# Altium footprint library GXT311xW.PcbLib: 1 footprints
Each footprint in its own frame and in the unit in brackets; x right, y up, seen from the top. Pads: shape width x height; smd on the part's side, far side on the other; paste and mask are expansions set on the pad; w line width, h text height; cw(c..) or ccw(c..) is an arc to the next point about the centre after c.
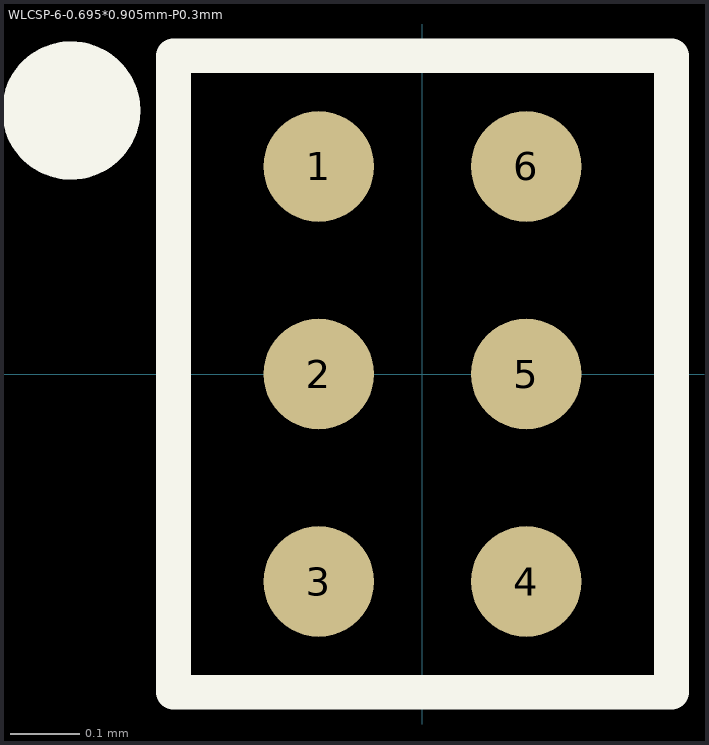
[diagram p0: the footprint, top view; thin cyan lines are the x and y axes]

## WLCSP-6-0.695*0.905mm-P0.3mm [mm]
height 0.55
pads (6):
  round 0.16 smd mask+0.05: 1(-0.15,0.3) 2(-0.15,0) 3(-0.15,-0.3) 4(0.15,-0.3) 5(0.15,0) 6(0.15,0.3)
Top Overlay:
  circle w0.1: c-0.508,0.381 r0.05
  lines w0.05: -0.36,-0.46 0.36,-0.46 0.36,0.46 -0.36,0.46 -0.36,-0.46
